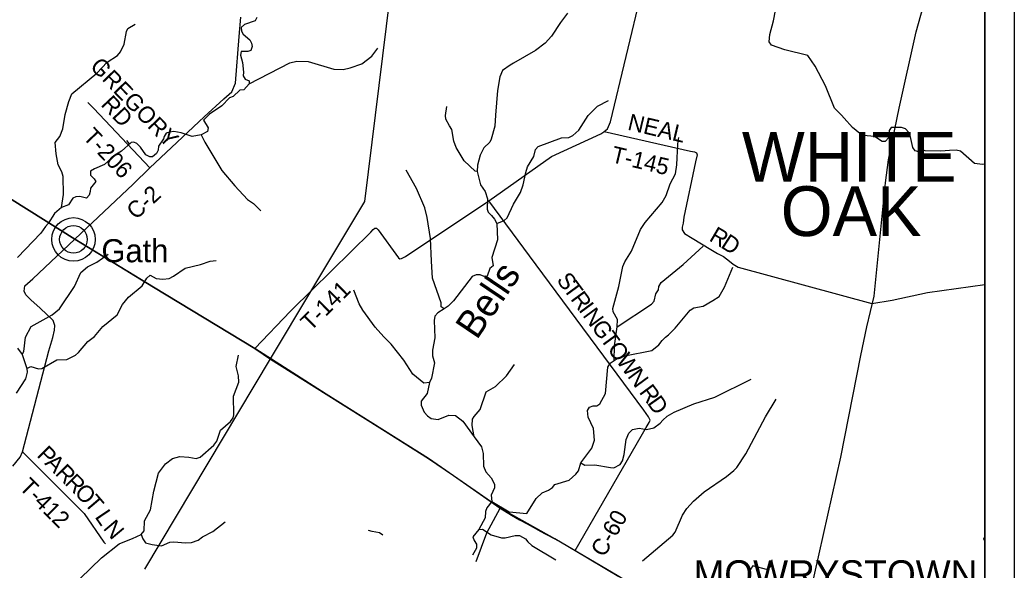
# Model space of a CAD drawing. Extents: x 0 to 34, y 0 to 22.
# Drawn here: x 5.601 to 9, y 16.162 to 18.045 of the extents above; entities that cross this region are included whole.
import ezdxf

# ---------------------------------------------------------------- set-up
doc = ezdxf.new("R2010")
doc.units = 0
for name, color, linetype in [('Default', 7, 'Continuous'), ('GM_X_Corporation_Text', 7, 'Continuous'), ('GM_X_County_Road', 7, 'Continuous'), ('GM_X_County_Road_Text', 7, 'Continuous'), ('GM_X_Minor_Lake', 7, 'Continuous'), ('GM_X_Minor_River', 7, 'Continuous'), ('GM_X_Minor_River_Text', 7, 'Continuous'), ('GM_X_Rail_Line', 7, 'Continuous'), ('GM_X_State_Route', 7, 'Continuous'), ('GM_X_Township_Road', 7, 'Continuous'), ('GM_X_Township_Road_Text', 7, 'Continuous'), ('GM_X_Township_Text', 7, 'Continuous'), ('GM_X_Unincorporated', 7, 'Continuous'), ('GM_X_Unincorporated_Location', 7, 'Continuous'), ('GM_X_Unincorporated_Text', 7, 'Continuous'), ('SH_Cut_Line', 7, 'Continuous'), ('SH_Data', 7, 'Continuous')]:
    doc.layers.add(name, color=color, linetype=linetype)

msp = doc.modelspace()

# ---------------------------------------------------------------- linework, layer by layer
at = {"layer": 'Default'}
for points in [[(6.0279, 16.166), (6.4581, 16.885), (6.5994, 17.1212), (6.7802, 17.4233), (6.9652, 18.9204)], [(8.161, 15.8436), (7.9019, 15.9854), (7.7478, 16.0791), (7.6481, 16.1403), (7.4293, 16.2693), (7.2434, 16.3742), (6.998, 16.5438), (6.6485, 16.765), (6.4043, 16.9203), (6.0579, 17.1312), (5.7891, 17.2948), (5.4666, 17.4969), (4.8712, 17.8663), (4.7185, 17.9622), (4.6135, 18.0087), (4.4868, 18.0434), (4.3784, 18.0545), (4.2056, 18.0659), (3.9354, 18.0836), (3.6991, 18.1432)]]:
    msp.add_lwpolyline(points, dxfattribs=at)
at = {"layer": 'GM_X_County_Road'}
for points in [[(7.5979, 17.6627), (7.5987, 17.6632), (7.6099, 17.6725), (7.6201, 17.697), (7.8343, 18.5916)], [(5.7891, 17.2948), (5.9881, 17.4834), (6.0448, 17.5393), (6.2308, 17.7141), (6.2982, 17.7754), (6.326, 17.7995), (6.3382, 17.8284), (6.3508, 17.9888), (6.3563, 18.0541)], [(7.2043, 17.426), (7.4188, 17.5774), (7.5875, 17.6555), (7.5979, 17.6627)], [(7.4992, 16.2294), (7.742, 16.65), (7.7522, 16.668), (7.7557, 16.6759), (7.7499, 16.6874), (7.7339, 16.7093), (7.3438, 17.2378), (7.2043, 17.426)], [(5.5768, 16.5178), (5.6024, 16.5484), (5.6102, 16.5671), (5.6997, 16.9122), (5.7141, 16.9585), (5.7191, 16.9831), (5.7201, 16.9994), (5.7151, 17.0165), (5.6707, 17.0587), (5.6389, 17.0878), (5.6218, 17.1048), (5.6155, 17.1166), (5.6181, 17.1355), (5.6455, 17.1597), (5.7891, 17.2948)]]:
    msp.add_lwpolyline(points, dxfattribs=at)
at = {"layer": 'GM_X_Minor_Lake'}
msp.add_lwpolyline([(8.9, 16.2756), (8.8954, 16.2708), (8.8961, 16.2674), (8.9, 16.2653)], dxfattribs=at)
at = {"layer": 'GM_X_Minor_River'}
for points in [[(8.6956, 17.5973), (8.6853, 17.6007), (8.6738, 17.5941), (8.6614, 17.5976), (8.6532, 17.6088), (8.6446, 17.6498), (8.6406, 17.6601), (8.6286, 17.672), (8.6146, 17.6776), (8.5793, 17.6769), (8.5727, 17.6668), (8.5713, 17.6425), (8.5597, 17.629), (8.5487, 17.6296), (8.5231, 17.6466), (8.4852, 17.6502), (8.472, 17.6564), (8.448, 17.6776), (8.4189, 17.7095), (8.4095, 17.7191), (8.3863, 17.7434), (8.3555, 17.82), (8.32, 17.8873), (8.2951, 17.9233), (8.2161, 17.9433), (8.1711, 17.9588), (8.1626, 17.9703), (8.1648, 17.9949), (8.1776, 18.0417), (8.1984, 18.1495)], [(6.4105, 18.0536), (6.405, 18.0419), (6.3692, 18.0295), (6.358, 18.0198), (6.359, 18.0069), (6.3638, 17.9966), (6.3867, 17.9769), (6.3933, 17.9651), (6.3955, 17.9544), (6.3903, 17.9401), (6.38, 17.9368), (6.3577, 17.9375), (6.3548, 17.9251), (6.3625, 17.8999), (6.365, 17.8661), (6.3641, 17.8536), (6.3711, 17.8422), (6.3843, 17.8367), (6.3853, 17.826), (6.3669, 17.8062), (6.3532, 17.8049), (6.3297, 17.7832), (6.3171, 17.7781), (6.2917, 17.7515), (6.2496, 17.7222), (6.2288, 17.702), (6.2448, 17.6764), (6.2423, 17.6639), (6.2213, 17.6521), (6.1901, 17.6465), (6.152, 17.6588), (6.1277, 17.6633), (6.1122, 17.6616), (6.1015, 17.6572), (6.0945, 17.6467), (6.092, 17.6379)], [(7.4736, 18.0684), (7.4489, 18.0361), (7.4182, 17.9892), (7.397, 17.9652), (7.3641, 17.9406), (7.2887, 17.8969), (7.2772, 17.8907), (7.2504, 17.8721), (7.2421, 17.8502), (7.2339, 17.8037), (7.2274, 17.7188), (7.2242, 17.6821), (7.2122, 17.6368), (7.2075, 17.627), (7.1875, 17.6072), (7.1751, 17.5827), (7.1658, 17.5476), (7.164, 17.5263), (7.1755, 17.4803), (7.1912, 17.4577), (7.1992, 17.4333), (7.1987, 17.3973), (7.202, 17.3878), (7.2132, 17.3759), (7.224, 17.3628), (7.2321, 17.3483), (7.2344, 17.2929), (7.2146, 17.2318), (7.2191, 17.204), (7.2076, 17.1943), (7.1989, 17.1687), (7.1879, 17.1677), (7.1743, 17.1724), (7.161, 17.1726), (7.1473, 17.1671), (7.0839, 17.0839), (7.0654, 17.0659), (7.052, 17.057), (7.0302, 17.0433), (7.0194, 17.0309), (7.017, 17.0169), (7.0195, 16.9577), (7.0121, 16.9154), (7.0115, 16.8957), (7.018, 16.8713), (7.0081, 16.8187), (7.0015, 16.804), (6.993, 16.7666), (6.9729, 16.7403), (6.9731, 16.7267), (6.9826, 16.7023), (6.9942, 16.69), (7.0066, 16.6811), (7.0308, 16.6777), (7.0675, 16.6923), (7.0902, 16.6913), (7.1153, 16.6716), (7.1545, 16.6187), (7.179, 16.5842), (7.1851, 16.5617), (7.1864, 16.5181), (7.1945, 16.499), (7.2121, 16.4782), (7.2231, 16.4561), (7.2241, 16.4435), (7.212, 16.4191), (7.214, 16.397), (7.1977, 16.3753), (7.1926, 16.3624), (7.1919, 16.3408), (7.1697, 16.3013), (7.15, 16.2762), (7.1537, 16.264), (7.1626, 16.2506), (7.1616, 16.2373), (7.1484, 16.214)], [(5.7437, 17.4035), (5.7499, 17.4477), (5.7485, 17.5099), (5.7445, 17.5248), (5.7324, 17.5496), (5.7249, 17.5872), (5.7216, 17.6255), (5.7371, 17.6462), (5.7473, 17.6722), (5.7556, 17.7217), (5.7679, 17.7659), (5.7785, 17.7923), (5.8645, 17.8627), (5.8992, 17.9005), (5.9344, 17.9231), (5.9448, 17.9355), (5.9573, 17.9622), (5.9651, 18.0053), (5.9698, 18.0155), (5.9954, 18.0307)], [(6.3853, 17.826), (6.524, 17.898), (6.5476, 17.904), (6.5866, 17.9026), (6.6746, 17.8772), (6.706, 17.8759), (6.7304, 17.8808), (6.7697, 17.8952), (6.8043, 17.9216), (6.8252, 17.9481)], [(7.164, 17.5263), (7.158, 17.5276), (7.1201, 17.5626), (7.0923, 17.6089), (7.0846, 17.6306), (7.078, 17.6701), (7.0698, 17.6824), (7.0572, 17.7057), (7.0559, 17.7186), (7.0605, 17.7493)], [(7.2321, 17.3483), (7.2562, 17.3586), (7.2673, 17.3679), (7.2885, 17.4146), (7.3122, 17.4545), (7.3213, 17.4805), (7.3306, 17.5228), (7.3369, 17.5428), (7.3575, 17.5778), (7.3639, 17.6012), (7.3728, 17.6117), (7.4529, 17.6413), (7.4772, 17.6432), (7.4917, 17.6495), (7.5121, 17.6678), (7.5443, 17.7181), (7.5762, 17.7506), (7.6137, 17.7691)], [(6.2213, 17.6521), (6.2335, 17.6269), (6.2913, 17.5294), (6.3362, 17.4779), (6.3795, 17.431), (6.3995, 17.4171), (6.4249, 17.3913)], [(7.6328, 16.8796), (7.6343, 16.9304), (7.6435, 16.9951), (7.6439, 17.0201), (7.6287, 17.0465), (7.6284, 17.0571), (7.6481, 17.1331), (7.6619, 17.2011), (7.669, 17.2173), (7.6923, 17.2538), (7.7225, 17.3284), (7.7384, 17.3525), (7.7963, 17.4203), (7.811, 17.4447), (7.8237, 17.4844), (7.8428, 17.5182), (7.8474, 17.5496), (7.8507, 17.6197), (7.8519, 17.6296), (7.8536, 17.6432)], [(6.092, 17.6379), (6.0747, 17.6133), (6.0738, 17.5996), (6.0675, 17.5876), (6.0548, 17.5768), (6.0454, 17.5769), (6.0318, 17.5839), (6.0132, 17.61), (6.0012, 17.6227), (5.991, 17.6273), (5.9815, 17.6256), (5.9485, 17.5965), (5.9256, 17.5828), (5.8902, 17.5503), (5.8559, 17.536), (5.8428, 17.5271), (5.8419, 17.5135), (5.855, 17.5019), (5.8602, 17.4924), (5.8428, 17.4695), (5.8411, 17.4585), (5.8383, 17.4453), (5.8287, 17.4356), (5.8064, 17.4412), (5.7923, 17.4399), (5.782, 17.4355), (5.7673, 17.4122), (5.7437, 17.4035), (5.7199, 17.3826), (5.6978, 17.3488), (5.6889, 17.3383), (5.6723, 17.3158), (5.593, 17.2324)], [(5.9761, 17.6208), (5.9665, 17.633)], [(8.9, 17.551), (8.892, 17.5501), (8.8648, 17.5544), (8.817, 17.5957), (8.8022, 17.5997), (8.7787, 17.5982), (8.7491, 17.5957), (8.6956, 17.5973)], [(7.052, 17.057), (7.0411, 17.0636), (7.0417, 17.0765), (7.0114, 17.1611), (7.008, 17.2199), (7.0049, 17.2969), (6.9938, 17.3691), (6.9855, 17.4026), (6.9572, 17.4683), (6.922, 17.5306)], [(7.6435, 16.9951), (7.7603, 17.0727), (7.7692, 17.0828), (7.7756, 17.1078), (7.7846, 17.1217), (7.7855, 17.1334), (7.7932, 17.1469), (7.8689, 17.2077), (7.9365, 17.2708)], [(5.609, 16.8998), (5.6148, 16.911), (5.62, 16.9599), (5.6395, 16.9964), (5.7113, 17.0355), (5.737, 17.056), (5.7882, 17.1325), (5.8097, 17.1804), (5.8323, 17.2005), (5.8637, 17.2167), (5.9031, 17.2435)], [(5.6243, 16.8525), (5.6384, 16.8595), (5.6641, 16.8516), (5.6755, 16.8521), (5.7271, 16.8817), (5.7616, 16.8835), (5.791, 16.8982), (5.8014, 16.9072), (5.8334, 16.945), (5.8556, 16.9617), (5.8849, 16.9962), (5.9336, 17.0356), (5.9516, 17.0718), (5.9724, 17.0965), (6.0185, 17.1349), (6.0355, 17.1612), (6.0459, 17.1712), (6.0674, 17.1603), (6.0901, 17.1577), (6.1118, 17.1608), (6.1263, 17.1678), (6.1665, 17.196), (6.2186, 17.2082), (6.251, 17.2191), (6.2723, 17.2214)], [(7.214, 16.397), (7.2734, 16.3617), (7.334, 16.3562), (7.3659, 16.407), (7.387, 16.4268), (7.4084, 16.4364), (7.4218, 16.4453), (7.4303, 16.455), (7.4787, 16.4707), (7.5021, 16.4912), (7.5107, 16.5024), (7.5182, 16.5289), (7.5558, 16.5799), (7.5649, 16.6075), (7.562, 16.6466), (7.5436, 16.6856), (7.542, 16.7083), (7.5486, 16.7204), (7.5612, 16.7247), (7.573, 16.7242), (7.5833, 16.7313), (7.6032, 16.767), (7.6105, 16.8564), (7.6194, 16.8703), (7.6328, 16.8796), (7.6435, 16.887), (7.6691, 16.8958), (7.7619, 16.9134), (7.7857, 16.9328), (7.7966, 16.9482), (7.8085, 16.959), (7.8181, 16.9672), (7.8412, 16.9904), (7.8925, 17.0515), (7.9055, 17.0597), (7.9367, 17.066), (7.97, 17.0845), (7.9911, 17.0986), (8.0097, 17.131), (8.0387, 17.1992)], [(7.0015, 16.804), (6.9817, 16.802), (6.9446, 16.8329), (6.9141, 16.8811), (6.8701, 16.9352), (6.8447, 16.9606), (6.8155, 16.994), (6.7738, 17.0515), (6.7612, 17.0741), (6.7422, 17.1202)], [(5.5926, 16.9224), (5.609, 16.8998), (5.6243, 16.8525), (5.6264, 16.8396), (5.6204, 16.8166), (5.5878, 16.7681)], [(5.8067, 16.1331), (5.8805, 16.2048), (5.9407, 16.2517), (5.9716, 16.2649), (5.9857, 16.27), (6.0155, 16.2843), (6.0255, 16.2967), (6.0271, 16.3308), (6.0473, 16.3685), (6.0592, 16.432), (6.0745, 16.4936), (6.0992, 16.5258), (6.1226, 16.5445), (6.1481, 16.5513), (6.1784, 16.5486), (6.2042, 16.5448), (6.2175, 16.5491), (6.2636, 16.5894), (6.274, 16.6033), (6.2863, 16.6418), (6.3213, 16.6713), (6.3298, 16.6833), (6.3326, 16.6938), (6.3308, 16.7572), (6.3493, 16.8051), (6.3484, 16.8267), (6.3402, 16.8591), (6.3483, 16.8984)], [(7.1545, 16.6187), (7.1474, 16.6571), (7.1481, 16.6787), (7.1535, 16.6885), (7.1747, 16.7117), (7.1949, 16.7721), (7.2271, 16.7909), (7.2644, 16.8276), (7.2915, 16.8663)], [(7.5182, 16.5289), (7.5322, 16.5215), (7.5667, 16.5221), (7.6205, 16.513), (7.6311, 16.5129), (7.6529, 16.5232), (7.661, 16.536), (7.6666, 16.5579), (7.6734, 16.6098), (7.6828, 16.6305), (7.6948, 16.644), (7.718, 16.6486), (7.743, 16.6437), (7.7685, 16.6497), (7.7896, 16.665), (7.7996, 16.6751), (7.8138, 16.6889), (7.8375, 16.703), (7.9055, 16.7312), (7.9764, 16.7545), (8.101, 16.8157)], [(7.7291, 16.1943), (7.8331, 16.282), (7.8413, 16.2921), (7.866, 16.3498), (7.8811, 16.3735), (7.9035, 16.3979), (7.9403, 16.4303), (8.017, 16.4824), (8.0419, 16.5033), (8.0519, 16.5134), (8.0833, 16.5599), (8.1504, 16.6868), (8.1861, 16.7474)], [(6.0155, 16.2843), (6.0209, 16.2695), (6.031, 16.256), (6.0529, 16.2497), (6.0855, 16.245), (6.1141, 16.2575), (6.127, 16.2595), (6.1671, 16.2555), (6.188, 16.2564), (6.2105, 16.2651), (6.2255, 16.2763), (6.261, 16.2944), (6.3032, 16.3275)], [(6.8416, 16.2817), (6.83, 16.2895), (6.8054, 16.2948), (6.7929, 16.2976)], [(7.1697, 16.3013), (7.1826, 16.3019), (7.2123, 16.2829), (7.2471, 16.2725), (7.26, 16.2727), (7.2943, 16.2809), (7.3087, 16.2804), (7.3294, 16.2694), (7.3372, 16.2595), (7.3511, 16.246), (7.4331, 16.197)], [(8.1712, 16.1979), (8.1659, 16.1722), (8.1537, 16.1648), (8.1064, 16.1769), (8.0983, 16.1656), (8.0881, 16.1138), (8.0788, 16.1017), (8.0627, 16.0906), (8.0264, 16.0695), (8.0055, 16.0444), (8.0012, 16.0319), (8.005, 16.0087), (8.0161, 15.988), (8.0347, 15.9627), (8.043, 15.9323)]]:
    msp.add_lwpolyline(points, dxfattribs=at)
at = {"layer": 'GM_X_Rail_Line'}
msp.add_lwpolyline([(6.7762, 14.3109), (6.9297, 14.4507), (7.5373, 15.0047), (7.83, 15.2691), (7.9287, 15.3625), (7.9592, 15.3949), (8.0363, 15.4875), (8.1684, 15.6475), (8.1886, 15.6755), (8.2095, 15.7107), (8.2296, 15.7554), (8.4079, 16.5494), (8.4762, 16.897), (8.4969, 16.9945), (8.5214, 17.0999), (8.5608, 17.4879), (8.571, 17.5663), (8.6067, 17.7431), (8.6649, 18.0046), (8.6886, 18.0902), (8.7141, 18.1631), (8.8658, 18.463), (8.9, 18.5325)], dxfattribs=at)
at = {"layer": 'GM_X_State_Route'}
for points in [[(4.4538, 18.0482), (4.4868, 18.0434), (4.5096, 18.0381), (4.5691, 18.0228), (4.6135, 18.0087), (4.6702, 17.9855), (4.7185, 17.9622), (4.7704, 17.9294), (4.8712, 17.8663), (4.9685, 17.8039), (5.0472, 17.7563), (5.2128, 17.6483), (5.4666, 17.4969), (5.7891, 17.2948), (5.8999, 17.2273), (6.0579, 17.1312), (6.4043, 16.9203)], [(6.4043, 16.9203), (6.4583, 16.8845), (6.6485, 16.765), (6.8411, 16.6434), (6.998, 16.5438), (7.0834, 16.4858), (7.2434, 16.3742), (7.2812, 16.3503), (7.2955, 16.3424), (7.3094, 16.3349), (7.3352, 16.3206), (7.3562, 16.3094), (7.3801, 16.2959), (7.3991, 16.2856), (7.4293, 16.2693), (7.4627, 16.2511), (7.4861, 16.2376), (7.4992, 16.2294), (7.6481, 16.1403)]]:
    msp.add_lwpolyline(points, dxfattribs=at)
at = {"layer": 'GM_X_Township_Road'}
for points in [[(6.0448, 17.5393), (5.8542, 17.7419), (5.833, 17.7628)], [(7.5987, 17.6632), (7.8932, 17.596), (7.9069, 17.5939), (7.9136, 17.5903), (7.9162, 17.5831), (7.9105, 17.5597), (7.8703, 17.37), (7.8681, 17.3491), (7.8656, 17.3363), (7.8647, 17.3272), (7.8728, 17.3138), (7.8991, 17.2985), (7.9633, 17.2598), (7.9863, 17.2464), (8.0069, 17.2355), (8.0272, 17.2199), (8.0391, 17.2098), (8.0568, 17.1996), (8.5132, 17.0745), (8.5829, 17.0865), (8.7041, 17.1123), (8.9, 17.1395)], [(6.5308, 17.053), (6.5996, 17.1207), (6.801, 17.3186), (6.8091, 17.3276), (6.8141, 17.332), (6.8206, 17.333), (6.8262, 17.3272), (6.8955, 17.2308), (6.8997, 17.228), (6.9061, 17.2287), (6.9195, 17.2353), (7.2043, 17.426)], [(6.4043, 16.9203), (6.5267, 17.0489), (6.5308, 17.053)], [(5.6102, 16.5671), (5.8076, 16.3703), (5.8203, 16.3564), (5.8876, 16.2575), (5.8938, 16.2524)], [(7.1605, 16.1917), (7.1971, 16.2901), (7.2434, 16.3742)]]:
    msp.add_lwpolyline(points, dxfattribs=at)
at = {"layer": 'GM_X_Unincorporated'}
for radius in [0.0744, 0.0472]:
    msp.add_circle((5.7842, 17.2942), radius, dxfattribs=at)
at = {"layer": 'GM_X_Unincorporated_Location'}
msp.add_line((5.7842, 17.2942), (5.7842, 17.2942), dxfattribs=at)
at = {"layer": 'SH_Cut_Line'}
msp.add_lwpolyline([(2.3212, 18.6531), (2.2797, 17.8302), (2.2668, 17.0936), (2.2632, 16.8811), (2.258, 16.7775), (2.1837, 15.746), (2.1, 14.637), (2.1, 14.4457), (2.4012, 14.4298), (2.4436, 14.4284), (2.5802, 14.4232), (3.783, 14.3901), (4.0144, 14.3862), (4.819, 14.3535), (4.9366, 14.3421), (5.0616, 14.3309), (5.4793, 14.3187), (6.7418, 14.3069), (6.8864, 14.3056), (7.3204, 14.3032), (8.6074, 14.2911), (8.7041, 14.2905), (8.9, 14.2922), (8.9, 20.8941)], dxfattribs=at)
at = {"layer": 'SH_Data'}
for p, q in [((9, 21), (9, 14)), ((8.9, 20.9), (8.9, 14.1))]:
    msp.add_line(p, q, dxfattribs=at)

# ---------------------------------------------------------------- texts
at = {"layer": 'GM_X_Corporation_Text'}
msp.add_text('MOWRYSTOWN', height=0.0947, rotation=0, dxfattribs=at).set_placement((7.9038, 16.1012))
at = {"layer": 'GM_X_County_Road_Text'}
for s, height, rotation, p in [('C-2', 0.05682, 42.7407, (5.998, 17.3589)), ('S', 0.0568, 306.3444, (7.4336, 17.155)), ('T', 0.0568, 306.3459, (7.4563, 17.1241)), ('R', 0.0568, 306.3469, (7.4815, 17.0899)), ('I', 0.0568, 306.3453, (7.5092, 17.0523)), ('N', 0.0568, 306.3446, (7.523, 17.0335)), ('G', 0.0568, 306.3451, (7.5526, 16.9932)), ('T', 0.0568, 306.3459, (7.5823, 16.953)), ('O', 0.0568, 306.3446, (7.6075, 16.9187)), ('W', 0.0568, 306.3465, (7.6371, 16.8785)), ('N', 0.0568, 306.3446, (7.6761, 16.8254)), ('R', 0.0568, 306.3328, (7.7161, 16.7711)), ('D', 0.0568, 305.2684, (7.7436, 16.7337)), ('C-60', 0.05682, 60.2126, (7.5988, 16.2036))]:
    msp.add_text(s, height=height, rotation=rotation, dxfattribs=at).set_placement(p)
at = {"layer": 'GM_X_Minor_River_Text'}
msp.add_text('Bells', height=0.09465, rotation=55.928, dxfattribs=at).set_placement((7.1629, 16.9476))
at = {"layer": 'GM_X_Township_Road_Text'}
for s, height, rotation, p in [('GREGORY', 0.05682, 313.9949, (5.8377, 17.8833)), ('RD', 0.05682, 313.2646, (5.8753, 17.7537)), ('NEAL', 0.05682, 346.7145, (7.6757, 17.67)), ('T-206', 0.05682, 313.4094, (5.8131, 17.6423)), ('T-145', 0.05682, 346.6464, (7.6195, 17.5591)), ('R', 0.0568, 329.5754, (7.9542, 17.2917)), ('D', 0.0568, 327.002, (7.9939, 17.2684)), ('T-141', 0.05682, 44.6048, (6.5949, 16.9775)), ('P', 0.0568, 314.869, (5.6564, 16.5534)), ('A', 0.0568, 314.8661, (5.6835, 16.5262)), ('R', 0.0568, 314.868, (5.7188, 16.4908)), ('R', 0.0568, 314.8694, (5.7517, 16.4577)), ('T-412', 0.05682, 315.0004, (5.5959, 16.4429)), ('O', 0.0568, 314.4294, (5.7845, 16.4247)), ('T', 0.0568, 310.4421, (5.8188, 16.3898)), ('L', 0.0568, 304.0728, (5.8556, 16.3446)), ('N', 0.0568, 309.9487, (5.8833, 16.3043))]:
    msp.add_text(s, height=height, rotation=rotation, dxfattribs=at).set_placement(p)
at = {"layer": 'GM_X_Township_Text'}
for s, p in [('WHITE', (8.0693, 17.4913)), ('OAK', (8.2022, 17.3056))]:
    msp.add_text(s, height=0.17045, rotation=0, dxfattribs=at).set_placement(p)
at = {"layer": 'GM_X_Unincorporated_Text'}
msp.add_text('Gath', height=0.07898, rotation=0, dxfattribs=at).set_placement((5.8798, 17.2159))

doc.saveas('drawing.dxf')
